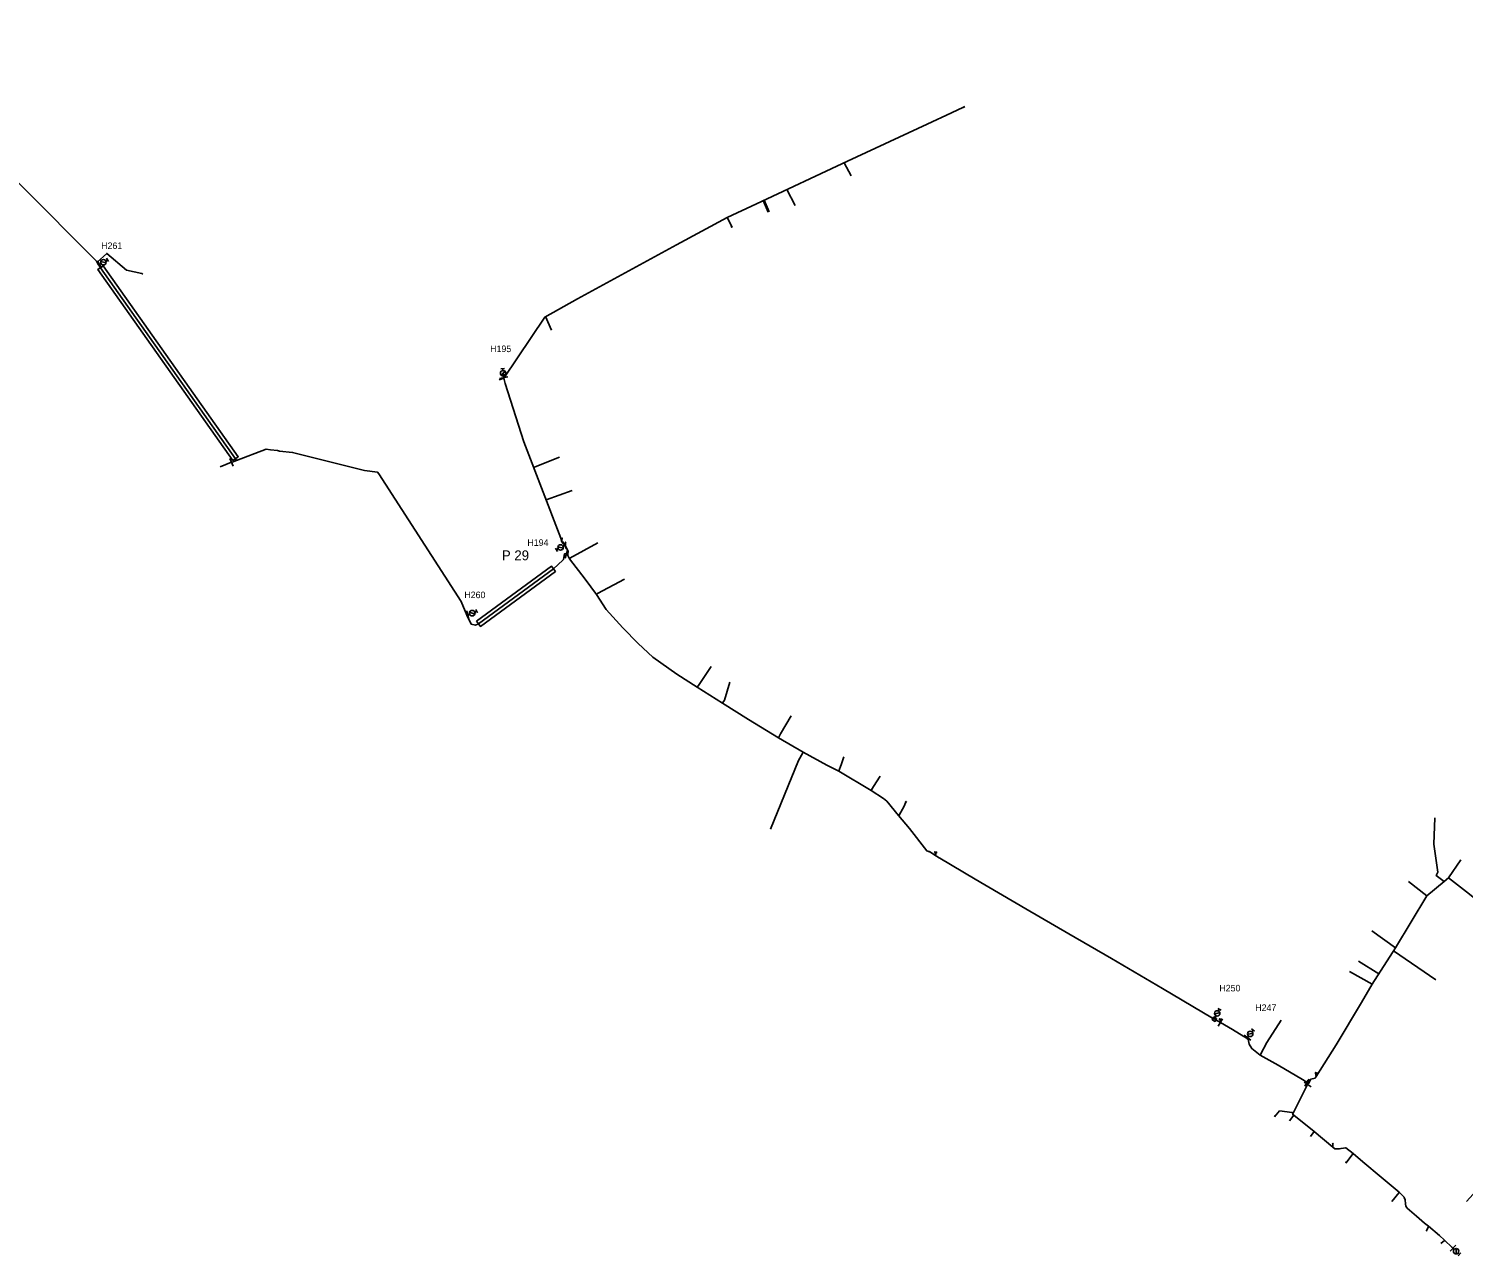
# Model space of a CAD drawing. Extents: x -548873 to -538270, y -1201997 to -1192514.
# Drawn here: x -545318.1 to -544882.1, y -1193277.6 to -1192904.4 of the extents above; entities that cross this region are included whole.
import ezdxf

# ---------------------------------------------------------------- set-up
doc = ezdxf.new("R2010")
doc.units = 0
for name, color, linetype in [('KN_HRAN_STÁTNÍ', 7, 'Continuous'), ('KN_PARC_Č', 7, 'Continuous'), ('KN_VKP_HRAN_SPORNÁ', 7, 'Continuous'), ('PK_PARC_Čv', 7, 'Continuous'), ('Vrstva 29', 7, 'Continuous'), ('Vrstva 37', 7, 'Continuous'), ('Vrstva 39', 7, 'Continuous')]:
    doc.layers.add(name, color=color, linetype=linetype)

# ---------------------------------------------------------------- blocks, each defined once
blk = doc.blocks.new('160')
at = {"layer": 'KN_HRAN_STÁTNÍ'}
blk.add_circle((0, 0), 0.0458, dxfattribs=at)
blk = doc.blocks.new('147')
at = {"layer": 'KN_HRAN_STÁTNÍ'}
blk.add_line((0, 1.27), (0, -1.27), dxfattribs=at)
blk = doc.blocks.new('133')
at = {"layer": 'KN_HRAN_STÁTNÍ'}
for p, q in [((0.28, 0), (0, 0)), ((0.54, 0.58), (1.7, -0.58)), ((1.94, 0), (2.52, 0)), ((2.52, 0.58), (2.52, -0.58))]:
    blk.add_line(p, q, dxfattribs=at)
blk.add_circle((1.11, 0), 0.825, dxfattribs=at)
blk = doc.blocks.new('150')
at = {"layer": 'KN_HRAN_STÁTNÍ'}
blk.add_line((0, 1.27), (0, -1.27), dxfattribs=at)
blk = doc.blocks.new('124')
at = {"layer": 'KN_HRAN_STÁTNÍ'}
for q in [(-0.19, 1.22), (-0.19, 0.92), (0.19, 1.22), (0, 0), (0.19, 0.92)]:
    blk.add_line((0, 1.07), q, dxfattribs=at)
blk = doc.blocks.new('123')
at = {"layer": 'KN_HRAN_STÁTNÍ'}
for p, q in [((-0.26, 0.96), (0.26, 0.96)), ((-0.19, 1.13), (0.19, 0.79)), ((-0.19, 0.79), (0, 0.96)), ((0, 1.22), (0, 0.96)), ((0, 0.96), (0.19, 1.13)), ((0, 0.96), (0, 0))]:
    blk.add_line(p, q, dxfattribs=at)
blk = doc.blocks.new('128')
at = {"layer": 'KN_HRAN_STÁTNÍ'}
for p, q in [((-0.19, 1.06), (-0.43, 1.15)), ((-0.36, 0.84), (-0.19, 1.06)), ((-0.19, 1.06), (-0.02, 1.25)), ((-0.19, 1.06), (0, 0)), ((0.05, 0.95), (-0.19, 1.06)), ((-0.1, 1), (0.41, 0.91)), ((-0.07, 0.82), (0.17, 0.96)), ((0.17, 0.96), (-0.02, 1.13)), ((0.17, 0.96), (0, 0)), ((0.19, 1.21), (0.17, 0.96)), ((0.17, 0.96), (0.38, 1.08)), ((0.36, 0.77), (0.17, 0.96))]:
    blk.add_line(p, q, dxfattribs=at)

msp = doc.modelspace()

# ---------------------------------------------------------------- linework, layer by layer
at = {"layer": 'KN_PARC_Č'}
for points in [[(-545034.043, -1192928.281), (-545033.59, -1192928.07)], [(-545033.816, -1192928.176), (-545033.64, -1192928.361)], [(-545070.239, -1192945.147), (-545068.117, -1192949.103)], [(-545094.919, -1192956.648), (-545093.428, -1192960.179)], [(-545094.572, -1192956.486), (-545093.045, -1192960.053)], [(-545087.742, -1192953.303), (-545085.176, -1192958.184)], [(-545105.853, -1192961.742), (-545104.344, -1192964.864)], [(-545104.475, -1192964.594), (-545104.738, -1192964.738)], [(-545297.371, -1192975.376), (-545297.35, -1192975.36), (-545294.42, -1192972.71), (-545288.42, -1192977.77), (-545283.73, -1192978.81), (-545283.467, -1192979.047)], [(-545161.03, -1192991.942), (-545159.231, -1192996.023)], [(-545173.737, -1193010.65), (-545175.123, -1193011.164)], [(-545167.655, -1193030.063), (-545167.454, -1193029.99)], [(-545164.673, -1193037.803), (-545156.838, -1193034.625)], [(-545160.871, -1193047.673), (-545152.942, -1193044.75)], [(-545153.77, -1193065.54), (-545153.63, -1193065.39), (-545145.138, -1193060.698)], [(-545145.59, -1193076.39), (-545145.46, -1193076.3), (-545145.24, -1193076.08), (-545137.093, -1193071.761)], [(-545114.97, -1193104.62), (-545114.86, -1193104.47), (-545114.31, -1193103.78), (-545110.673, -1193098.292)], [(-545107.27, -1193109.42), (-545107.19, -1193109.28), (-545106.64, -1193108.51), (-545104.992, -1193103.047)], [(-545090.24, -1193119.95), (-545090.19, -1193119.82), (-545089.61, -1193118.79), (-545086.412, -1193113.273)], [(-545082.71, -1193124.38), (-545082.9, -1193124.6), (-545084.189, -1193126.852), (-545092.71, -1193147.79)], [(-545071.94, -1193130.12), (-545071.87, -1193130), (-545071.16, -1193128.2), (-545070.42, -1193125.74)], [(-545062.04, -1193135.96), (-545061.95, -1193135.78), (-545061.33, -1193134.84), (-545059.37, -1193131.61)], [(-545053.74, -1193143.61), (-545053.62, -1193143.51), (-545052.01, -1193140.74), (-545051.46, -1193139.26)], [(-545051.53, -1193139.449), (-545051.682, -1193139.262)], [(-545051.53, -1193139.449), (-545051.303, -1193139.359)], [(-545051.53, -1193139.449), (-545051.272, -1193139.535)], [(-544887.965, -1193163.666), (-544890.381, -1193161.847), (-544889.889, -1193160.795), (-544891.065, -1193152.314), (-544890.811, -1193144.319)], [(-544886.598, -1193162.583), (-544882.905, -1193157.057)], [(-544893.185, -1193167.985), (-544898.77, -1193163.694)], [(-544902.737, -1193183.81), (-544909.946, -1193178.646)], [(-544907.76, -1193191.713), (-544913.988, -1193187.863)], [(-544903.314, -1193184.718), (-544890.469, -1193193.525)], [(-544909.795, -1193194.917), (-544916.728, -1193190.988)], [(-544943.91, -1193216.47), (-544943.8, -1193216.27), (-544941.81, -1193212.67), (-544937.435, -1193205.792)], [(-544939.328, -1193234.977), (-544939.614, -1193234.876)], [(-544933.816, -1193234.117), (-544934.127, -1193233.898), (-544937.95, -1193233.385), (-544939.508, -1193235.185)], [(-544933.607, -1193234.74), (-544934.915, -1193236.422)], [(-544927.451, -1193239.672), (-544928.611, -1193241.171)], [(-544917.67, -1193249.122), (-544917.92, -1193248.955)], [(-544915.55, -1193246.41), (-544917.855, -1193249.358)], [(-544901.582, -1193258.173), (-544901.64, -1193258.24), (-544903.852, -1193260.987)], [(-544892.671, -1193268.457), (-544892.73, -1193268.53), (-544893.311, -1193269.878), (-544893.419, -1193270)], [(-544887.801, -1193272.732), (-544887.869, -1193272.79), (-544888.988, -1193273.743)]]:
    msp.add_lwpolyline(points, dxfattribs=at)
at = {"layer": 'KN_VKP_HRAN_SPORNÁ'}
for points in [[(-545255, -1193035.68), (-545255.25, -1193035.12), (-545296.34, -1192977.05), (-545296.63, -1192976.58), (-545296.86, -1192976.21), (-545297.54, -1192975.1), (-545297.55, -1192975.07), (-545366.21, -1192906.11), (-545367.82, -1192904.39)], [(-545173.745, -1193010.617), (-545161.268, -1192992.076), (-545151.35, -1192986.478), (-545133.5, -1192976.772), (-545121.26, -1192970.117), (-545105.88, -1192961.755), (-545096.952, -1192957.595), (-545069.235, -1192944.679), (-545045.112, -1192933.439), (-545037.664, -1192929.968), (-545034.043, -1192928.281)], [(-545156.07, -1193060.4), (-545156.38, -1193059.33), (-545167.66, -1193030.05), (-545173.33, -1193012.24), (-545173.745, -1193010.617)], [(-545154.71, -1193064.14), (-545154.82, -1193064.08), (-545155.25, -1193064.03), (-545155.63, -1193065.79), (-545155.76, -1193066.01), (-545158.61, -1193068.57), (-545158.65, -1193068.59), (-545181.41, -1193085.33), (-545181.45, -1193085.36), (-545182.36, -1193085.74), (-545183.65, -1193085.4), (-545184.94, -1193082.69), (-545186.68, -1193078.56), (-545211.74, -1193039.7), (-545212.07, -1193039.26), (-545216.06, -1193038.7), (-545237.91, -1193033.2), (-545241.94, -1193032.79), (-545242.5, -1193032.65), (-545244.6, -1193032.4), (-545245.95, -1193032.22), (-545255, -1193035.68)], [(-545256.49, -1193036.23), (-545259.89, -1193037.61)], [(-545255, -1193035.68), (-545256.27, -1193036.16), (-545256.49, -1193036.23)], [(-545155, -1193061.69), (-545155.161, -1193061.364), (-545155.36, -1193060.97), (-545155.84, -1193060.79), (-545156.07, -1193060.4)], [(-545154.24, -1193064.161), (-545154.24, -1193064.16), (-545154.15, -1193063.36), (-545154.6, -1193062.48), (-545155, -1193061.69)], [(-545154.24, -1193064.161), (-545154.71, -1193064.14)], [(-545044.4, -1193154.631), (-545045.17, -1193154.36), (-545050.41, -1193147.59), (-545053.74, -1193143.61), (-545057.34, -1193139.24), (-545058.31, -1193138.44), (-545062.04, -1193135.96), (-545071.94, -1193130.12), (-545075.567, -1193128.291), (-545082.71, -1193124.38), (-545090.24, -1193119.95), (-545099.38, -1193114.43), (-545107.27, -1193109.42), (-545114.97, -1193104.62), (-545121.18, -1193100.68), (-545128.42, -1193095.48), (-545132.93, -1193091.33), (-545137.51, -1193086.58), (-545142.63, -1193080.95), (-545145.59, -1193076.39), (-545149.05, -1193071.77), (-545153.77, -1193065.54), (-545154.28, -1193064.56), (-545154.24, -1193064.161)], [(-545042.485, -1193155.808), (-545044.232, -1193154.643), (-545044.4, -1193154.631)], [(-544955.966, -1193206.568), (-544956.66, -1193206.169), (-544957.513, -1193205.643), (-544957.852, -1193205.437), (-544958.223, -1193205.23), (-544958.322, -1193205.186), (-544973.532, -1193196.211), (-544989.055, -1193187.107), (-545002.041, -1193179.555), (-545015.042, -1193171.942), (-545030.501, -1193162.956), (-545041.232, -1193156.629), (-545041.431, -1193156.512), (-545042.236, -1193155.975), (-545042.485, -1193155.808)], [(-544881.11, -1193260.99), (-544878.076, -1193257.632), (-544869.975, -1193248.421), (-544867.019, -1193245.046), (-544859.515, -1193234.824), (-544856.401, -1193226.265), (-544851.714, -1193209.535), (-544851.702, -1193209.494), (-544849.817, -1193202.414), (-544849.8, -1193202.142), (-544853.214, -1193196.164), (-544855.03, -1193192.807), (-544859.852, -1193186.483), (-544865.085, -1193179.621), (-544865.348, -1193179.412), (-544881.16, -1193166.867), (-544886.663, -1193162.532), (-544887.958, -1193163.66), (-544893.185, -1193167.984), (-544902.737, -1193183.81), (-544909.795, -1193194.916), (-544913.024, -1193200.427), (-544920.746, -1193213.299), (-544926.86, -1193222.93)], [(-544947.867, -1193211.371), (-544948.072, -1193211.234), (-544948.791, -1193210.799), (-544952.319, -1193208.665), (-544955.966, -1193206.568)], [(-544929.6, -1193224.8), (-544930.95, -1193223.89), (-544938.418, -1193219.525), (-544943.91, -1193216.47), (-544946.39, -1193214.45), (-544947.21, -1193213.17), (-544947.54, -1193211.58), (-544947.867, -1193211.371)], [(-544926.86, -1193222.93), (-544927.047, -1193223.216), (-544927.15, -1193223.44), (-544928.51, -1193223.81), (-544929.2, -1193225.05)], [(-544929.45, -1193225.37), (-544929.72, -1193225.84), (-544933.816, -1193234.116), (-544934.005, -1193234.421), (-544933.607, -1193234.74), (-544927.451, -1193239.672), (-544921.75, -1193244.46)], [(-544929.2, -1193225.05), (-544929.6, -1193224.8)], [(-544929.2, -1193225.05), (-544929.45, -1193225.37)], [(-544921.75, -1193244.46), (-544921.19, -1193244.91), (-544919.83, -1193244.99), (-544919.28, -1193244.85), (-544918.56, -1193244.79), (-544917.86, -1193244.61), (-544915.55, -1193246.41), (-544912.69, -1193248.93), (-544907.07, -1193253.61), (-544901.579, -1193258.176), (-544900.15, -1193259.63), (-544900.05, -1193259.79), (-544899.77, -1193260.44), (-544899.69, -1193261.72), (-544899.57, -1193262.36), (-544899.17, -1193262.97), (-544896.35, -1193265.44), (-544893.89, -1193267.54), (-544892.671, -1193268.457), (-544889.33, -1193271.26), (-544887.8, -1193272.733), (-544885.471, -1193274.975)]]:
    msp.add_lwpolyline(points, dxfattribs=at)
at = {"layer": 'PK_PARC_Čv'}
for points in [[(-545296.86, -1192976.21), (-545296.58, -1192976.06), (-545296.38, -1192975.95)], [(-545173.745, -1193010.617), (-545173.77, -1193010.52), (-545173.8, -1193010.23)], [(-545155.161, -1193061.364), (-545155.521, -1193061.567)], [(-545184.94, -1193082.69), (-545184.63, -1193082.66), (-545184.36, -1193082.56)], [(-544957.952, -1193204.851), (-544958.438, -1193205.725), (-544957.579, -1193206.236), (-544957.093, -1193205.362), (-544957.952, -1193204.851)], [(-544957.852, -1193205.437), (-544957.466, -1193204.744)], [(-544947.852, -1193211.381), (-544947.75, -1193211.14), (-544947.55, -1193210.88)], [(-544885.471, -1193274.975), (-544885.12, -1193275.313)]]:
    msp.add_lwpolyline(points, dxfattribs=at)
at = {"layer": 'Vrstva 37'}
for points in [[(-545295.524, -1192976.472), (-545254.434, -1193034.542), (-545256.066, -1193035.698), (-545297.156, -1192977.628), (-545295.524, -1192976.472)], [(-545182.002, -1193084.524), (-545159.242, -1193067.784), (-545158.058, -1193069.396), (-545180.818, -1193086.136), (-545182.002, -1193084.524)]]:
    msp.add_lwpolyline(points, dxfattribs=at)

# ---------------------------------------------------------------- block references
at = {"layer": 'PK_PARC_Čv'}
for name, p, xscale, yscale, rotation in [('133', (-545296.38, -1192975.95), 1.0037042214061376, 1.0037042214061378, 29.379208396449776), ('150', (-545296.58, -1192976.06), 1.0037042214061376, 1.0037042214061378, 29.379208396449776), ('133', (-545173.8, -1193010.23), 1.0011217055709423, 1.0011217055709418, 96.5826098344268), ('150', (-545173.77, -1193010.52), 0.999999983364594, 0.9999999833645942, 101.0000002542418), ('133', (-545155.521, -1193061.567), 0.9999999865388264, 0.9999999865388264, -149.99999955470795), ('150', (-545155.26, -1193061.42), 0.9999999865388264, 0.9999999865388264, 30.00000044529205), ('150', (-545184.63, -1193082.66), 1.0028916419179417, 1.0028916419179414, 13.69720873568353), ('133', (-545184.36, -1193082.56), 1.0275072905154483, 1.027507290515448, 24.689105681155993), ('133', (-544957.466, -1193204.744), 1.0000000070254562, 1.0000000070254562, 61.000001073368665), ('133', (-544947.55, -1193210.88), 0.9999999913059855, 0.9999999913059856, 52.999998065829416), ('150', (-544947.75, -1193211.14), 0.9999999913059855, 0.9999999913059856, 52.999998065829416), ('150', (-544885.3, -1193275.14), 1.00000000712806, 1.00000000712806, -43.0000005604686), ('133', (-544885.12, -1193275.313), 1.00000000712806, 1.00000000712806, -43.0000005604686)]:
    msp.add_blockref(name, p, dxfattribs=dict(at, xscale=xscale, yscale=yscale, rotation=rotation))
at = {"layer": 'Vrstva 29'}
for name, p, xscale, yscale, rotation in [('160', (-545034.043, -1192928.281), 1.0169562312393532, 1.016956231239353, 26.97601645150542), ('160', (-545173.745, -1193010.617), 1.0000000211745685, 1.0000000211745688, -98.99999960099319), ('147', (-545256.49, -1193036.23), 1.0296949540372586, 1.0296949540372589, -155.86620948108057), ('160', (-545255, -1193035.68), 0.9999999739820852, 0.9999999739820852, 111.00000058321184), ('160', (-545156.07, -1193060.4), 1.019856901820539, 1.0198569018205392, 26.393983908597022), ('160', (-545155, -1193061.69), 0.9999999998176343, 0.9999999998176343, 116.9999993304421), ('147', (-545154.71, -1193064.14), 0.999999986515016, 0.9999999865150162, 164.99999987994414), ('160', (-545154.24, -1193064.161), 1.000000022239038, 1.0000000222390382, -94.99999998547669), ('160', (-545044.4, -1193154.631), 1.0060666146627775, 1.0060666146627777, 167.3452647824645), ('160', (-545042.485, -1193155.808), 0.9999999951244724, 0.9999999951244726, 146.99999872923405), ('147', (-544955.966, -1193206.568), 1.0037042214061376, 1.0037042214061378, 150.62079160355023), ('160', (-544947.867, -1193211.371), 0.9999999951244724, 0.9999999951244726, 146.99999872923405), ('160', (-544926.86, -1193222.93), 0.9999999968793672, 0.9999999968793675, 57.99999972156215), ('147', (-544929.45, -1193225.37), 0.9999999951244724, 0.9999999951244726, 56.999998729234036), ('147', (-544929.6, -1193224.8), 0.9999999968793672, 0.9999999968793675, 147.99999972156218), ('160', (-544929.2, -1193225.05), 0.9999999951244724, 0.9999999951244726, 56.999998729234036), ('160', (-544921.75, -1193244.46), 1.000000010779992, 1.0000000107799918, -38.9999989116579), ('160', (-544885.471, -1193274.975), 1.00000000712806, 1.00000000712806, -43.0000005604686)]:
    msp.add_blockref(name, p, dxfattribs=dict(at, xscale=xscale, yscale=yscale, rotation=rotation))
at = {"layer": 'Vrstva 39'}
for name, p in [('128', (-545173.745, -1193010.617)), ('123', (-545156.07, -1193060.4)), ('124', (-545155, -1193061.69)), ('128', (-545042.485, -1193155.808)), ('128', (-544955.966, -1193206.568)), ('128', (-544926.86, -1193222.93)), ('124', (-544929.45, -1193225.37)), ('124', (-544921.75, -1193244.46))]:
    msp.add_blockref(name, p, dxfattribs=at)

# ---------------------------------------------------------------- texts
at = {"layer": 'PK_PARC_Čv'}
for s, height, p in [('H261', 2, (-545296.09, -1192971.39)), ('H195', 2, (-545177.87, -1193002.72)), ('H194', 2, (-545166.551, -1193061.627)), ('P 29', 3, (-545174.311, -1193066.007)), ('H260', 2, (-545185.72, -1193077.53)), ('H250', 2, (-544956.266, -1193197.094)), ('H247', 2, (-544945.35, -1193203.05))]:
    msp.add_text(s, height=height, dxfattribs=at).set_placement(p)

doc.saveas('drawing.dxf')
